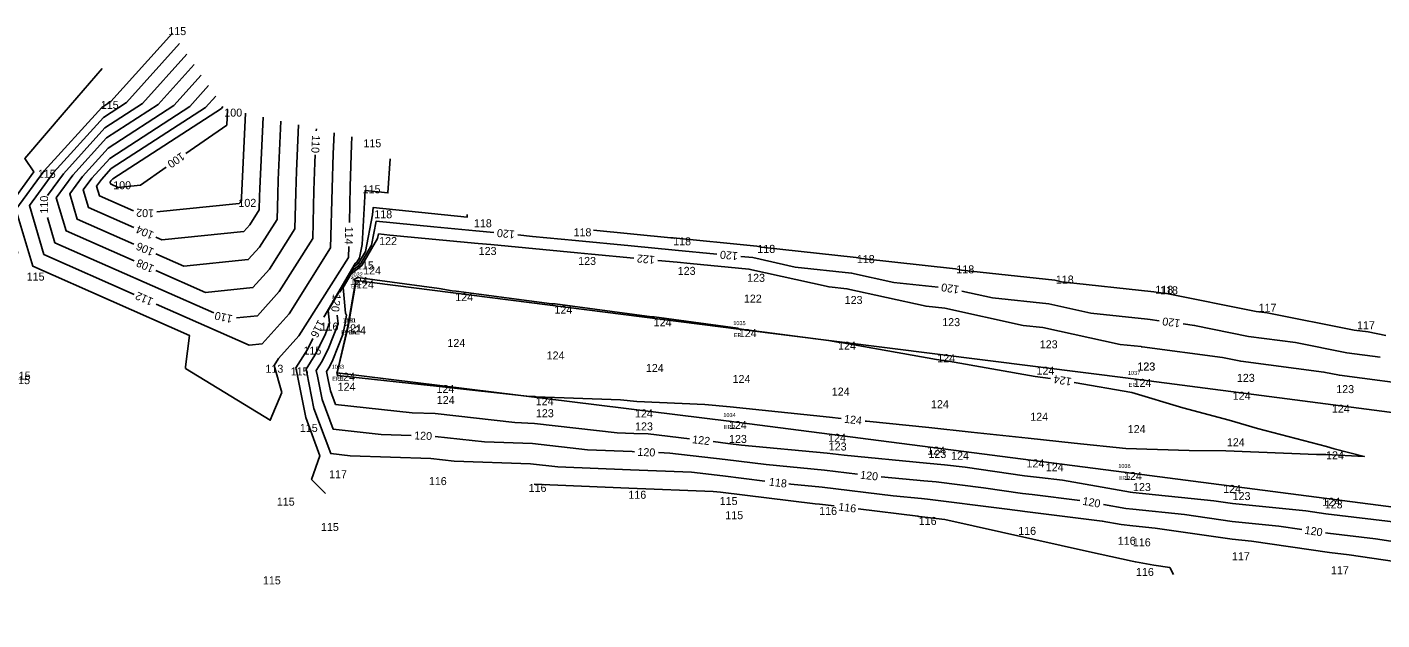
# Model space of a CAD drawing. Extents: x 2080741 to 2082054, y 730754 to 730981.
# Drawn here: x 2081487.2 to 2081825.8, y 730780.5 to 730928.7 of the extents above; entities that cross this region are included whole.
import ezdxf

# ---------------------------------------------------------------- set-up
doc = ezdxf.new("R2010")
doc.units = 0
for name, color, linetype in [('Default', 7, 'Continuous'), ('RD_DTM_Major1', 7, 'Continuous'), ('RD_DTM_Major1_Lbl', 7, 'Continuous'), ('RD_DTM_Minor1', 7, 'Continuous'), ('RD_DTM_Minor2_Lbl', 7, 'Continuous'), ('RD_EX_Road', 7, 'Continuous'), ('RD_EX_Road_txCode', 7, 'Continuous'), ('RD_SMD_Locator', 7, 'Continuous')]:
    doc.layers.add(name, color=color, linetype=linetype)

msp = doc.modelspace()

# ---------------------------------------------------------------- linework, layer by layer
at = {"layer": 'RD_DTM_Major1'}
for points in [[(2081527.13, 730921.92), (2081516.01, 730909.57), (2081506.66, 730903.5), (2081496.26, 730892.02), (2081492.28, 730886.58)], [(2081536.16, 730908.78), (2081535.76, 730908.34), (2081508.62, 730890.73), (2081508.16, 730890.22), (2081507.94, 730889.9), (2081508.07, 730889.45), (2081509.98, 730888.61), (2081515.53, 730889.17), (2081521.97, 730893.64)], [(2081526.9, 730897.07), (2081537.13, 730904.18), (2081537.32, 730908.11)], [(2081559.47, 730902.71), (2081559.5, 730903.22)], [(2081539.52, 730855.98), (2081544.77, 730856.51), (2081550.22, 730862.57), (2081558.59, 730875.84), (2081558.9, 730887.8), (2081559.1, 730894.83), (2081559.19, 730896.72)], [(2081492.29, 730881.11), (2081494.16, 730874.76), (2081533.85, 730857.24)], [(2081603.85, 730877.31), (2081599.37, 730877.75), (2081588.84, 730878.74), (2081574.47, 730880.17), (2081573.31, 730874.19), (2081570.45, 730869.35), (2081568.52, 730867.83), (2081565.33, 730862.39)], [(2081659.59, 730871.89), (2081649.17, 730872.92), (2081638.21, 730873.96), (2081624.27, 730875.34), (2081613.51, 730876.35), (2081609.82, 730876.72)], [(2081714.89, 730863.65), (2081703.83, 730864.84), (2081693.26, 730867.18), (2081679.19, 730868.68), (2081668.6, 730871.04), (2081665.56, 730871.32)], [(2081770.18, 730855.24), (2081767.92, 730855.55), (2081767.25, 730855.62), (2081767.23, 730855.63), (2081753.11, 730857.18), (2081742.57, 730859.47), (2081728.47, 730861.01), (2081720.8, 730862.69)], [(2081564.7, 730856.68), (2081564.91, 730854.48), (2081562.62, 730848.54), (2081560.93, 730845.18), (2081559.48, 730842.86), (2081559.79, 730841.4), (2081560.95, 730835.54), (2081563.69, 730828.18), (2081575.69, 730826.86), (2081583.22, 730826.61)], [(2081825.41, 730846.19), (2081817.06, 730847.27), (2081804.25, 730849.81), (2081792.48, 730851.36), (2081778.99, 730854.07), (2081776.13, 730854.45)], [(2081589.21, 730826.36), (2081601.52, 730824.99), (2081613.54, 730824.55), (2081627.3, 730822.98), (2081638.45, 730822.54), (2081639.03, 730822.52)], [(2081645.02, 730822.28), (2081647.86, 730822.17), (2081661.71, 730820.54), (2081671.92, 730819.29), (2081686.54, 730817.91), (2081694.72, 730816.91)], [(2081700.69, 730816.26), (2081711.37, 730815.24), (2081714.4, 730814.95), (2081726.21, 730813.49), (2081735.96, 730812.11), (2081738.43, 730811.82), (2081750.33, 730810.35)], [(2081756.25, 730809.35), (2081761.83, 730808.36), (2081763.6, 730808.15), (2081776.49, 730806.85), (2081788.43, 730805.11), (2081800.06, 730803.93), (2081805.84, 730803.09)], [(2081811.77, 730802.22), (2081812.31, 730802.15), (2081824.21, 730800.7), (2081836.82, 730798.86), (2081849.05, 730797.39), (2081860.49, 730802.21)]]:
    msp.add_lwpolyline(points, dxfattribs=at)
at = {"layer": 'RD_DTM_Minor1'}
for points in [[(2081523.52, 730927.17), (2081508.1, 730910.06), (2081505.87, 730908.61), (2081491.5, 730892.74), (2081484.42, 730883.06), (2081488.6, 730868.89), (2081527.78, 730851.59), (2081526.82, 730843.72), (2081526.78, 730843.36), (2081547.96, 730830.37), (2081550.83, 730837.28), (2081548.92, 730844.04), (2081550.07, 730845.83), (2081555.12, 730851.45), (2081567.51, 730871.09), (2081567.58, 730873.83)], [(2081525.33, 730924.55), (2081512.06, 730909.82), (2081506.27, 730906.06), (2081493.88, 730892.38), (2081487.78, 730884.04), (2081491.38, 730871.83), (2081513.99, 730861.85)], [(2081506, 730918.35), (2081496.49, 730907.28), (2081486.64, 730895.81), (2081488.87, 730892.5), (2081482.17, 730883.19), (2081481.93, 730882.17), (2081484.87, 730872.03)], [(2081528.94, 730919.29), (2081519.96, 730909.32), (2081507.05, 730900.95), (2081498.64, 730891.66), (2081494.5, 730885.99), (2081496.95, 730877.7), (2081513.92, 730870.21)], [(2081530.74, 730916.66), (2081523.91, 730909.08), (2081507.44, 730898.39), (2081501.02, 730891.3), (2081497.86, 730886.97), (2081499.73, 730880.64), (2081513.88, 730874.39)], [(2081532.55, 730914.03), (2081527.86, 730908.83), (2081507.84, 730895.84), (2081503.4, 730890.94), (2081501.22, 730887.95), (2081502.51, 730883.58), (2081513.85, 730878.57)], [(2081534.35, 730911.41), (2081531.81, 730908.58), (2081508.23, 730893.28), (2081505.78, 730890.58), (2081504.58, 730888.93), (2081505.29, 730886.51), (2081513.81, 730882.75)], [(2081519.64, 730882.46), (2081540.2, 730884.57), (2081540.42, 730884.81), (2081540.75, 730885.34), (2081540.76, 730885.81), (2081540.77, 730886.09), (2081541.75, 730907.13)], [(2081519.34, 730876.15), (2081520.89, 730875.46), (2081541.34, 730877.55), (2081542.87, 730879.25), (2081545.21, 730882.96), (2081545.3, 730886.31), (2081545.35, 730888.28), (2081546.19, 730906.15)], [(2081519.37, 730871.96), (2081526.34, 730868.89), (2081542.49, 730870.54), (2081545.32, 730873.69), (2081549.67, 730880.59), (2081549.83, 730886.81), (2081549.94, 730890.46), (2081550.62, 730905.17)], [(2081519.41, 730867.78), (2081531.79, 730862.32), (2081543.63, 730863.53), (2081547.77, 730868.13), (2081554.13, 730878.21), (2081554.37, 730887.3), (2081554.52, 730892.65), (2081555.06, 730904.2)], [(2081519.48, 730859.42), (2081542.69, 730849.17), (2081545.91, 730849.5), (2081552.67, 730857.01), (2081563.05, 730873.46), (2081563.44, 730888.29), (2081563.69, 730897.01), (2081563.93, 730902.24)], [(2081567.74, 730879.83), (2081567.98, 730888.79), (2081568.27, 730899.2), (2081568.37, 730901.26)], [(2081577.97, 730895.76), (2081577.38, 730887.2), (2081571.69, 730887.78), (2081570.92, 730874.33), (2081570.28, 730871), (2081569.64, 730869.92), (2081569.2, 730869.57), (2081561.35, 730856.14)], [(2081597.23, 730881.82), (2081597.18, 730881.15), (2081573.67, 730883.55), (2081573.57, 730881.71), (2081571.79, 730872.6), (2081570.04, 730869.63), (2081568.86, 730868.7), (2081562.47, 730857.78), (2081562.77, 730854.64), (2081561.61, 730851.61), (2081559.09, 730846.62), (2081556.93, 730843.16), (2081557.12, 730842.28), (2081558.9, 730833.3), (2081563.08, 730822.03), (2081567.92, 730821.5), (2081588.07, 730820.83), (2081593.94, 730820.18), (2081613.05, 730819.48), (2081619.89, 730818.7), (2081638.01, 730817.98), (2081653.28, 730817.38), (2081661.1, 730816.46), (2081671.62, 730815.18)], [(2081638.84, 730870.92), (2081628.3, 730871.91), (2081624.77, 730872.26), (2081603.1, 730874.3), (2081599.91, 730874.61), (2081577.86, 730876.68), (2081575.05, 730876.96), (2081574.82, 730875.79), (2081570.86, 730869.07), (2081568.17, 730866.95), (2081566.17, 730863.53), (2081566.78, 730857.14), (2081567.07, 730856.69), (2081566.64, 730854.27), (2081566.08, 730851.81), (2081563.64, 730845.47), (2081562.78, 730843.75), (2081562.03, 730842.56), (2081562.46, 730840.52), (2081563.01, 730837.77), (2081564.29, 730834.32), (2081583.47, 730832.21), (2081589.17, 730832.03), (2081609.1, 730829.79), (2081614.04, 730829.61), (2081634.7, 730827.26), (2081638.89, 730827.09), (2081642.43, 730826.95), (2081652.75, 730825.74)], [(2081628.75, 730877.92), (2081648.11, 730876), (2081648.7, 730875.95), (2081668.78, 730873.96), (2081669.6, 730873.88), (2081670.72, 730873.63), (2081694.42, 730871.1), (2081695.76, 730870.8), (2081719.23, 730868.27), (2081720.77, 730867.93), (2081744.04, 730865.39), (2081745.78, 730865.01), (2081768.84, 730862.47), (2081768.84, 730862.47), (2081769.93, 730862.35), (2081771.97, 730862.08), (2081794.4, 730857.58), (2081797.18, 730857.22), (2081818.89, 730852.91), (2081822.39, 730852.46), (2081826.83, 730851.58)], [(2081841.92, 730837.95), (2081839.9, 730838.21), (2081836.64, 730838.85), (2081815.22, 730841.63), (2081811.32, 730842.41), (2081790.56, 730845.15), (2081786.01, 730846.06), (2081765.91, 730848.74), (2081765.66, 730848.77), (2081765.62, 730848.78), (2081760.44, 730849.35), (2081741.1, 730853.55), (2081736.16, 730854.09), (2081716.59, 730858.38), (2081711.9, 730858.88), (2081692.09, 730863.26), (2081687.66, 730863.73), (2081667.6, 730868.19), (2081652.89, 730869.58), (2081649.64, 730869.9), (2081644.81, 730870.35)], [(2081564.62, 730842.32), (2081564.66, 730842.39), (2081564.76, 730842.67), (2081567.34, 730853.89), (2081569.31, 730864.99), (2081568.92, 730865.58), (2081569.78, 730866.05), (2081590.16, 730863.34), (2081593.42, 730862.74), (2081594.46, 730862.67), (2081618.37, 730859.51), (2081619.22, 730859.46), (2081643.34, 730856.25), (2081643.97, 730856.21), (2081664.84, 730853.41), (2081665.11, 730853.27), (2081687.54, 730850.33), (2081689.88, 730849.91), (2081690.15, 730849.87), (2081714.52, 730845.58), (2081717.52, 730845.12), (2081739.17, 730841.36), (2081743.03, 730840.79)], [(2081558.64, 730850.81), (2081557.25, 730848.05), (2081554.38, 730843.45), (2081554.44, 730843.16), (2081556.85, 730831.06), (2081560.4, 730821.49), (2081558.32, 730815.59), (2081561.78, 730812.08)], [(2081690.7, 730830.84), (2081687.74, 730831.17), (2081670.89, 730832.88), (2081662.9, 730833.76), (2081656.6, 730834.32), (2081639.62, 730835.1), (2081635.53, 730835.45), (2081614.36, 730836.27), (2081614.11, 730836.29), (2081612.82, 730836.32), (2081589.52, 730838.93), (2081585.57, 730839.28), (2081564.74, 730841.55), (2081564.59, 730842.27), (2081564.62, 730842.32)], [(2081748.95, 730839.81), (2081763.32, 730837.34), (2081776.03, 730833.52), (2081787.65, 730830.4), (2081794.74, 730828.33), (2081812.02, 730823.81), (2081813.91, 730823.27), (2081821.42, 730821.35), (2081811.8, 730821.81), (2081809.51, 730821.84), (2081786.83, 730822.77), (2081777.64, 730822.79), (2081761.83, 730823.3), (2081748.94, 730824.63), (2081737.42, 730825.92), (2081723.13, 730827.38), (2081712.58, 730828.56), (2081697.04, 730830.14), (2081696.67, 730830.18)], [(2081658.71, 730825.04), (2081662.32, 730824.61), (2081665.79, 730824.19), (2081687.17, 730822.17), (2081691.4, 730821.65), (2081712.02, 730819.68), (2081716.54, 730819.25), (2081721.63, 730818.62), (2081736.5, 730816.51), (2081740.27, 730816.08), (2081746, 730815.37), (2081762.97, 730812.38), (2081763.61, 730812.3), (2081783.85, 730810.26), (2081788.48, 730809.59), (2081806.84, 730807.73), (2081811.85, 730807), (2081830.74, 730804.71), (2081836.21, 730803.91), (2081855.75, 730801.56), (2081857.14, 730802.15)], [(2081688.95, 730808.95), (2081685.29, 730809.4), (2081684.18, 730809.5), (2081660.49, 730812.38), (2081658.71, 730812.59), (2081637.56, 730813.43), (2081613.9, 730814.37)], [(2081677.57, 730814.46), (2081678.05, 730814.4), (2081685.91, 730813.65), (2081703.7, 730811.47), (2081710.73, 730810.8), (2081712.27, 730810.65), (2081730.79, 730808.36), (2081735.42, 730807.7), (2081736.59, 730807.57), (2081755.95, 730805.18), (2081760.69, 730804.34), (2081763.59, 730803.99), (2081769.13, 730803.43), (2081788.38, 730800.63), (2081793.27, 730800.14), (2081812.77, 730797.3), (2081817.67, 730796.7), (2081837.44, 730793.82), (2081842.36, 730793.23), (2081861.1, 730801.11), (2081862.17, 730800.98), (2081872.05, 730793.47)], [(2081773.76, 730791.8), (2081772.8, 730793.53), (2081768.85, 730794.18), (2081764.2, 730794.95), (2081763.37, 730795.14), (2081752.74, 730797.51), (2081716.57, 730805.56), (2081710.13, 730806.36), (2081710.08, 730806.36), (2081709.85, 730806.38), (2081694.91, 730808.22)]]:
    msp.add_lwpolyline(points, dxfattribs=at)
at = {"layer": 'RD_EX_Road'}
for points in [[(2081567.45, 730853.84), (2081569.41, 730865.32), (2081665.09, 730853.16), (2081763.75, 730840.72), (2081866.15, 730827.41), (2081946.59, 730817.06)], [(2081567.45, 730853.84), (2081564.7, 730842.25), (2081662.62, 730830.19), (2081761.36, 730817.44), (2081864.07, 730804.08), (2081944.33, 730793.7), (2082046, 730780.47)]]:
    msp.add_lwpolyline(points, dxfattribs=at)
at = {"layer": 'RD_SMD_Locator'}
for centre in [(2081569.41, 730865.32), (2081567.45, 730853.84), (2081567.45, 730853.84), (2081665.09, 730853.16), (2081564.7, 730842.25), (2081763.75, 730840.72), (2081662.62, 730830.19), (2081761.36, 730817.44)]:
    msp.add_circle(centre, 0.001, dxfattribs=at)

# ---------------------------------------------------------------- texts
at = {"layer": 'Default'}
for s, p in [('115', (2081522.49, 730926.67)), ('115', (2081505.62, 730908.22)), ('100', (2081536.49, 730906.29)), ('115', (2081571.26, 730898.62)), ('115', (2081489.88, 730890.99)), ('100', (2081508.72, 730888.13)), ('115', (2081571.06, 730887.13)), ('102', (2081540.01, 730883.73)), ('118', (2081573.98, 730880.88)), ('118', (2081598.88, 730878.63)), ('118', (2081623.78, 730876.37)), ('122', (2081575.19, 730874.18)), ('123', (2081600.07, 730871.7)), ('118', (2081648.68, 730874.12)), ('118', (2081669.72, 730872.22)), ('115', (2081569.4, 730868.08)), ('123', (2081624.94, 730869.21)), ('118', (2081694.59, 730869.66)), ('115', (2081487.1, 730865.3)), ('124', (2081571.2, 730866.83)), ('123', (2081649.82, 730866.73)), ('123', (2081667.17, 730864.99)), ('118', (2081719.46, 730867.11)), ('118', (2081744.33, 730864.56)), ('124', (2081567.86, 730864.16)), ('124', (2081569.41, 730863.32)), ('118', (2081769.2, 730862)), ('118', (2081770.38, 730861.88)), ('124', (2081594.21, 730860.17)), ('122', (2081666.36, 730859.79)), ('123', (2081691.55, 730859.45)), ('117', (2081795, 730857.5)), ('124', (2081619.01, 730857.02)), ('116', (2081560.55, 730852.8)), ('121', (2081566.45, 730852.37)), ('124', (2081567.45, 730851.84)), ('124', (2081643.81, 730853.86)), ('124', (2081665.09, 730851.16)), ('123', (2081715.93, 730853.91)), ('117', (2081819.61, 730853.12)), ('124', (2081592.25, 730848.7)), ('124', (2081689.89, 730848.03)), ('123', (2081740.31, 730848.36)), ('115', (2081556.28, 730846.8)), ('124', (2081617.06, 730845.57)), ('124', (2081714.7, 730844.9)), ('115', (2081483.62, 730840.54)), ('113', (2081546.77, 730842.26)), ('115', (2081553.08, 730841.6)), ('124', (2081641.86, 730842.44)), ('124', (2081739.5, 730841.77)), ('123', (2081764.68, 730842.82)), ('123', (2081764.74, 730842.81)), ('115', (2081483.47, 730839.41)), ('124', (2081564.7, 730840.25)), ('124', (2081564.82, 730837.75)), ('124', (2081589.52, 730837.2)), ('124', (2081663.53, 730839.7)), ('124', (2081763.75, 730838.72)), ('123', (2081789.58, 730839.98)), ('123', (2081814.42, 730837.16)), ('124', (2081589.6, 730834.44)), ('124', (2081614.33, 730834.14)), ('124', (2081688.33, 730836.55)), ('124', (2081788.54, 730835.49)), ('123', (2081614.38, 730831.14)), ('124', (2081639.14, 730831.08)), ('124', (2081713.13, 730833.4)), ('124', (2081813.33, 730832.27)), ('115', (2081555.37, 730827.46)), ('123', (2081639.16, 730827.84)), ('124', (2081662.62, 730828.19)), ('124', (2081737.93, 730830.25)), ('124', (2081762.3, 730827.16)), ('123', (2081662.64, 730824.71)), ('124', (2081687.41, 730824.99)), ('124', (2081787.08, 730823.88)), ('123', (2081687.57, 730822.82)), ('124', (2081712.2, 730821.79)), ('123', (2081712.49, 730820.94)), ('124', (2081718.16, 730820.51)), ('124', (2081811.87, 730820.61)), ('124', (2081737, 730818.59)), ('124', (2081741.82, 730817.65)), ('117', (2081562.68, 730815.88)), ('116', (2081587.62, 730814.17)), ('124', (2081761.36, 730815.44)), ('116', (2081612.56, 730812.46)), ('116', (2081637.49, 730810.75)), ('123', (2081763.62, 730812.68)), ('124', (2081786.15, 730812.22)), ('123', (2081788.52, 730810.43)), ('115', (2081549.62, 730809.03)), ('115', (2081660.31, 730809.19)), ('116', (2081685.18, 730806.7)), ('124', (2081810.94, 730808.99)), ('123', (2081811.53, 730808.35)), ('115', (2081661.7, 730805.65)), ('116', (2081710.06, 730804.21)), ('115', (2081560.64, 730802.69)), ('116', (2081734.93, 730801.72)), ('116', (2081759.81, 730799.24)), ('116', (2081763.58, 730798.86)), ('117', (2081788.34, 730795.38)), ('116', (2081764.36, 730791.45)), ('117', (2081813.1, 730791.9)), ('115', (2081546.13, 730789.35))]:
    msp.add_text(s, height=2, dxfattribs=at).set_placement(p)
at = {"layer": 'RD_DTM_Major1_Lbl'}
for s, rotation, p in [('110', 267.3247, (2081558.42, 730901.69)), ('100', 214.7924, (2081525.72, 730897.47)), ('110', 90.1018, (2081492.44, 730882.06)), ('120', 174.3259, (2081609.19, 730877.78)), ('120', 174.5603, (2081664.93, 730872.38)), ('120', 170.7821, (2081720.27, 730863.95)), ('120', 263.6703, (2081563.67, 730862.03)), ('110', 167.4161, (2081538.7, 730856.59)), ('120', 172.3926, (2081775.53, 730855.54)), ('120', 357.6649, (2081583.91, 730825.6)), ('120', 357.7333, (2081639.72, 730821.49)), ('120', 353.8153, (2081695.34, 730815.79)), ('120', 350.3194, (2081750.89, 730809.26)), ('120', 351.7062, (2081806.42, 730802))]:
    msp.add_text(s, height=2, rotation=rotation, dxfattribs=at).set_placement(p)
at = {"layer": 'RD_DTM_Minor2_Lbl'}
for s, rotation, p in [('102', 177.1873, (2081518.97, 730883.05)), ('104', 156.1776, (2081519.07, 730877.36)), ('114', 268.4964, (2081566.71, 730878.79)), ('106', 156.1776, (2081519.11, 730873.17)), ('108', 156.1776, (2081519.14, 730868.99)), ('122', 174.6222, (2081644.17, 730871.42)), ('112', 156.1776, (2081518.91, 730860.77)), ('116', 243.0818, (2081559.98, 730855.68)), ('124', 170.5825, (2081748.39, 730840.93)), ('124', 353.6683, (2081691.32, 730829.77)), ('122', 353.2896, (2081653.36, 730824.66)), ('118', 353.061, (2081672.55, 730814.06)), ('116', 353.0068, (2081689.88, 730807.83))]:
    msp.add_text(s, height=2, rotation=rotation, dxfattribs=at).set_placement(p)
at = {"layer": 'RD_EX_Road_txCode'}
for s, p in [('1032', (2081568.02, 730866.32)), ('EPL', (2081568.2, 730863.32)), ('EPRA', (2081565.73, 730851.84)), ('EPLA', (2081565.76, 730851.84)), ('1030', (2081566.02, 730854.84)), ('1031', (2081566.35, 730854.84)), ('1035', (2081663.71, 730854.16)), ('EPL', (2081663.89, 730851.16)), ('1033', (2081563.32, 730843.25)), ('1037', (2081762.36, 730841.72)), ('EPR', (2081563.47, 730840.25)), ('EPL', (2081762.54, 730838.72)), ('1034', (2081661.23, 730831.19)), ('EPR', (2081661.39, 730828.19)), ('1036', (2081759.95, 730818.44)), ('EPR', (2081760.13, 730815.44))]:
    msp.add_text(s, height=1, dxfattribs=at).set_placement(p)

doc.saveas('drawing.dxf')
